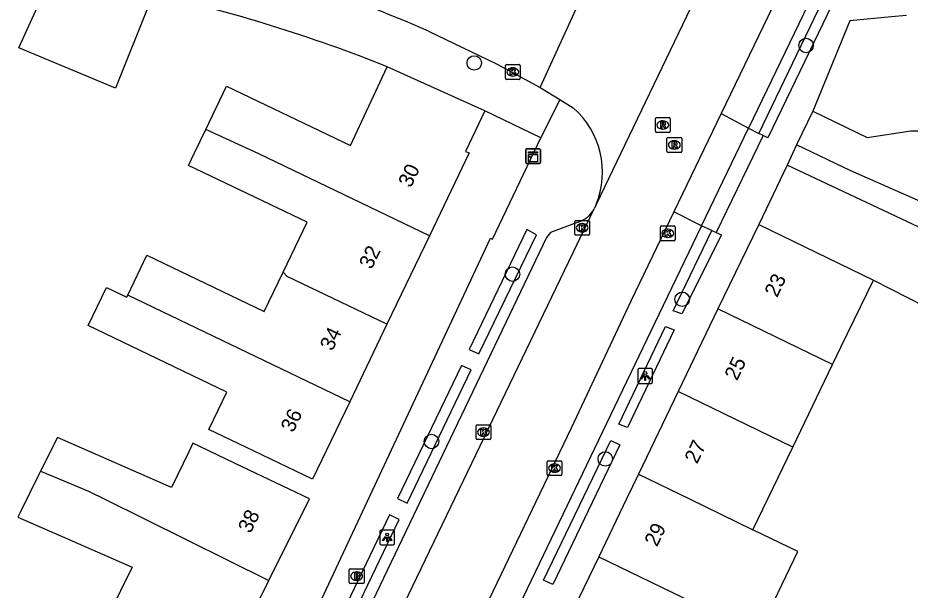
# Model space of a CAD drawing. Extents: x 163010 to 163853, y 382793 to 383982.
# Drawn here: x 163375.8 to 163436.2, y 383493.8 to 383532.5 of the extents above; entities that cross this region are included whole.
import ezdxf

# ---------------------------------------------------------------- set-up
doc = ezdxf.new("R2010")
doc.units = 0
for name, color, linetype in [('IMGEO_Boom', 7, 'Continuous'), ('IMGEO_Brandkraan', 7, 'Continuous'), ('IMGEO_Kast', 7, 'Continuous'), ('IMGEO_Kolk', 7, 'Continuous'), ('IMGEO_Lichtpunt', 7, 'Continuous'), ('IMGEO_Muur', 7, 'Continuous'), ('IMGEO_Pand', 7, 'Continuous'), ('IMGEO_Pand_nummerreeks', 7, 'Continuous'), ('IMGEO_Rijbaan_lokaal_gesloten', 7, 'Continuous'), ('IMGEO_Rijbaan_lokaal_onverhard', 7, 'Continuous'), ('IMGEO_Rijbaan_lokaal_open', 7, 'Continuous'), ('IMGEO_Rioolput', 7, 'Continuous'), ('IMGEO_Voetpad_open', 7, 'Continuous')]:
    doc.layers.add(name, color=color, linetype=linetype)

msp = doc.modelspace()

# ---------------------------------------------------------------- linework, layer by layer
at = {"layer": 'IMGEO_Boom'}
for centre in [(163429.168, 383530.666), (163406.72, 383529.486), (163409.304, 383515.2), (163420.79, 383513.503), (163403.821, 383503.888), (163415.582, 383502.708)]:
    msp.add_circle(centre, 0.489, dxfattribs=at)
at = {"layer": 'IMGEO_Brandkraan'}
for p, q in [((163398.259, 383494.356), (163398.259, 383495.208)), ((163398.334, 383495.282), (163399.186, 383495.282)), ((163398.747, 383495.062), (163398.772, 383495.062)), ((163399.26, 383495.208), (163399.26, 383494.356)), ((163398.77, 383494.502), (163398.745, 383494.502)), ((163399.186, 383494.282), (163398.334, 383494.282))]:
    msp.add_line(p, q, dxfattribs=at)
for points in [[(163398.259, 383494.356), (163398.259, 383495.208)], [(163398.334, 383495.282), (163399.186, 383495.282)], [(163398.607, 383494.982), (163398.607, 383494.582), (163398.82, 383494.582)], [(163398.838, 383494.982), (163398.607, 383494.982)], [(163399.26, 383495.208), (163399.26, 383494.356)], [(163398.786, 383494.901), (163398.732, 383494.901), (163398.732, 383494.825)], [(163398.732, 383494.825), (163398.785, 383494.825)], [(163398.794, 383494.749), (163398.732, 383494.749), (163398.732, 383494.668)], [(163398.732, 383494.668), (163398.794, 383494.668)], [(163399.186, 383494.282), (163398.334, 383494.282)]]:
    msp.add_lwpolyline(points, dxfattribs=at)
for centre, radius, start, end in [((163398.336, 383495.206), 0.0765, 91.55205, 178.44795), ((163398.336, 383495.206), 0.0765, 91.55205, 178.44795), ((163398.842, 383494.837), 0.145, 59.4692, 91.53667), ((163398.867, 383494.884), 0.0922, 285.51372, 58.15012), ((163399.184, 383495.206), 0.0765, 1.55205, 88.44795), ((163399.184, 383495.206), 0.0765, 1.55205, 88.44795), ((163398.336, 383494.358), 0.0765, 181.55205, 268.44795), ((163398.336, 383494.358), 0.0765, 181.55205, 268.44795), ((163398.787, 383494.863), 0.0379, 267.82845, 90.93552), ((163398.795, 383494.708), 0.0404, 269.87594, 90.50774), ((163398.826, 383494.833), 0.251, 268.66757, 293.53466), ((163398.872, 383494.692), 0.105, 301.31148, 78.98903), ((163399.184, 383494.358), 0.0765, 271.55205, 358.44795), ((163399.184, 383494.358), 0.0765, 271.55205, 358.44795)]:
    msp.add_arc(centre, radius, start, end, dxfattribs=at)
for centre, major_axis, ratio, start_param, end_param in [((163398.746, 383494.782), (-0.387, 0.002), 0.722429, 4.712389, 7.853982), ((163398.771, 383494.782), (-0.39, 0.002), 0.717154, 1.570796, 4.712389)]:
    msp.add_ellipse(centre, major_axis=major_axis, ratio=ratio, start_param=start_param, end_param=end_param, dxfattribs=at)
at = {"layer": 'IMGEO_Kast'}
for p, q in [((163410.195, 383522.751), (163410.195, 383523.592)), ((163410.195, 383523.592), (163410.195, 383522.751)), ((163410.27, 383523.676), (163411.111, 383523.676)), ((163411.111, 383523.676), (163410.27, 383523.676)), ((163411.195, 383523.601), (163411.195, 383522.76)), ((163411.195, 383522.76), (163411.195, 383523.601)), ((163411.12, 383522.676), (163410.279, 383522.676)), ((163410.279, 383522.676), (163411.12, 383522.676))]:
    msp.add_line(p, q, dxfattribs=at)
for points in [[(163410.39, 383523.466), (163410.99, 383523.466), (163410.99, 383523.381), (163410.39, 383523.381), (163410.39, 383523.466)], [(163410.39, 383523.291), (163410.99, 383523.291), (163410.99, 383522.802), (163410.39, 383522.802), (163410.39, 383523.291)]]:
    msp.add_lwpolyline(points, dxfattribs=at)
msp.add_circle((163410.474, 383523.14), 0.0377, dxfattribs=at)
for centre, start, end in [((163410.273, 383523.598), 92.4484, 184.28452), ((163410.273, 383523.598), 92.4484, 184.28452), ((163411.117, 383523.598), 2.4484, 94.28452), ((163411.117, 383523.598), 2.4484, 94.28452), ((163410.273, 383522.754), 182.4484, 274.28452), ((163410.273, 383522.754), 182.4484, 274.28452), ((163411.117, 383522.754), 272.4484, 4.28452), ((163411.117, 383522.754), 272.4484, 4.28452)]:
    msp.add_arc(centre, 0.0779, start, end, dxfattribs=at)
at = {"layer": 'IMGEO_Kolk'}
for p, q in [((163408.9, 383529.375), (163409.752, 383529.375)), ((163408.825, 383528.449), (163408.825, 383529.301)), ((163409.313, 383529.155), (163409.338, 383529.155)), ((163409.826, 383529.301), (163409.826, 383528.449)), ((163409.752, 383528.375), (163408.9, 383528.375)), ((163409.336, 383528.595), (163409.311, 383528.595)), ((163413.519, 383517.912), (163413.519, 383518.764)), ((163413.594, 383518.838), (163414.446, 383518.838)), ((163414.007, 383518.618), (163414.032, 383518.618)), ((163414.52, 383518.764), (163414.52, 383517.912)), ((163419.386, 383518.462), (163420.238, 383518.462)), ((163414.03, 383518.058), (163414.005, 383518.058)), ((163419.311, 383517.536), (163419.311, 383518.388)), ((163419.799, 383518.242), (163419.824, 383518.242)), ((163420.312, 383518.388), (163420.312, 383517.536)), ((163414.446, 383517.838), (163413.594, 383517.838)), ((163420.238, 383517.462), (163419.386, 383517.462)), ((163419.822, 383517.682), (163419.797, 383517.682)), ((163406.839, 383504.094), (163406.839, 383504.946)), ((163406.914, 383505.02), (163407.766, 383505.02)), ((163407.327, 383504.8), (163407.352, 383504.8)), ((163407.84, 383504.946), (163407.84, 383504.094)), ((163407.766, 383504.02), (163406.914, 383504.02)), ((163407.35, 383504.24), (163407.325, 383504.24)), ((163411.649, 383501.66), (163411.649, 383502.512)), ((163411.724, 383502.586), (163412.576, 383502.586)), ((163412.137, 383502.366), (163412.162, 383502.366)), ((163412.65, 383502.512), (163412.65, 383501.66)), ((163412.576, 383501.586), (163411.724, 383501.586)), ((163412.16, 383501.806), (163412.135, 383501.806))]:
    msp.add_line(p, q, dxfattribs=at)
for points in [[(163408.9, 383529.375), (163409.752, 383529.375)], [(163408.825, 383528.449), (163408.825, 383529.301)], [(163409.146, 383529.075), (163409.269, 383529.075), (163409.269, 383528.924), (163409.399, 383529.075), (163409.563, 383529.075), (163409.417, 383528.924), (163409.57, 383528.675), (163409.418, 383528.675), (163409.333, 383528.839), (163409.269, 383528.772), (163409.269, 383528.675), (163409.146, 383528.675), (163409.146, 383529.075)], [(163409.826, 383529.301), (163409.826, 383528.449)], [(163409.752, 383528.375), (163408.9, 383528.375)], [(163413.519, 383517.912), (163413.519, 383518.764)], [(163413.594, 383518.838), (163414.446, 383518.838)], [(163413.84, 383518.538), (163413.963, 383518.538), (163413.963, 383518.387), (163414.093, 383518.538), (163414.257, 383518.538), (163414.111, 383518.387), (163414.264, 383518.138), (163414.112, 383518.138), (163414.027, 383518.302), (163413.963, 383518.235), (163413.963, 383518.138), (163413.84, 383518.138), (163413.84, 383518.538)], [(163414.52, 383518.764), (163414.52, 383517.912)], [(163419.386, 383518.462), (163420.238, 383518.462)], [(163419.311, 383517.536), (163419.311, 383518.388)], [(163419.632, 383518.162), (163419.755, 383518.162), (163419.755, 383518.011), (163419.885, 383518.162), (163420.049, 383518.162), (163419.903, 383518.011), (163420.056, 383517.762), (163419.904, 383517.762), (163419.819, 383517.926), (163419.755, 383517.859), (163419.755, 383517.762), (163419.632, 383517.762), (163419.632, 383518.162)], [(163420.312, 383518.388), (163420.312, 383517.536)], [(163414.446, 383517.838), (163413.594, 383517.838)], [(163420.238, 383517.462), (163419.386, 383517.462)], [(163406.839, 383504.094), (163406.839, 383504.946)], [(163406.914, 383505.02), (163407.766, 383505.02)], [(163407.16, 383504.72), (163407.283, 383504.72), (163407.283, 383504.569), (163407.413, 383504.72), (163407.577, 383504.72), (163407.431, 383504.569), (163407.584, 383504.32), (163407.432, 383504.32), (163407.347, 383504.484), (163407.283, 383504.417), (163407.283, 383504.32), (163407.16, 383504.32), (163407.16, 383504.72)], [(163407.84, 383504.946), (163407.84, 383504.094)], [(163407.766, 383504.02), (163406.914, 383504.02)], [(163411.649, 383501.66), (163411.649, 383502.512)], [(163411.724, 383502.586), (163412.576, 383502.586)], [(163411.97, 383502.286), (163412.093, 383502.286), (163412.093, 383502.135), (163412.223, 383502.286), (163412.387, 383502.286), (163412.241, 383502.135), (163412.394, 383501.886), (163412.242, 383501.886), (163412.157, 383502.05), (163412.093, 383501.983), (163412.093, 383501.886), (163411.97, 383501.886), (163411.97, 383502.286)], [(163412.65, 383502.512), (163412.65, 383501.66)], [(163412.576, 383501.586), (163411.724, 383501.586)]]:
    msp.add_lwpolyline(points, dxfattribs=at)
for centre, start, end in [((163408.902, 383529.299), 91.55205, 178.44795), ((163408.902, 383529.299), 91.55205, 178.44795), ((163409.75, 383529.299), 1.55205, 88.44795), ((163409.75, 383529.299), 1.55205, 88.44795), ((163408.902, 383528.451), 181.55205, 268.44795), ((163408.902, 383528.451), 181.55205, 268.44795), ((163409.75, 383528.451), 271.55205, 358.44795), ((163409.75, 383528.451), 271.55205, 358.44795), ((163413.596, 383518.762), 91.55205, 178.44795), ((163413.596, 383518.762), 91.55205, 178.44795), ((163414.444, 383518.762), 1.55205, 88.44795), ((163414.444, 383518.762), 1.55205, 88.44795), ((163419.388, 383518.386), 91.55205, 178.44795), ((163419.388, 383518.386), 91.55205, 178.44795), ((163420.236, 383518.386), 1.55205, 88.44795), ((163420.236, 383518.386), 1.55205, 88.44795), ((163413.596, 383517.914), 181.55205, 268.44795), ((163413.596, 383517.914), 181.55205, 268.44795), ((163414.444, 383517.914), 271.55205, 358.44795), ((163414.444, 383517.914), 271.55205, 358.44795), ((163419.388, 383517.538), 181.55205, 268.44795), ((163419.388, 383517.538), 181.55205, 268.44795), ((163420.236, 383517.538), 271.55205, 358.44795), ((163420.236, 383517.538), 271.55205, 358.44795), ((163406.916, 383504.944), 91.55205, 178.44795), ((163406.916, 383504.944), 91.55205, 178.44795), ((163407.764, 383504.944), 1.55205, 88.44795), ((163407.764, 383504.944), 1.55205, 88.44795), ((163406.916, 383504.096), 181.55205, 268.44795), ((163406.916, 383504.096), 181.55205, 268.44795), ((163407.764, 383504.096), 271.55205, 358.44795), ((163407.764, 383504.096), 271.55205, 358.44795), ((163411.726, 383502.51), 91.55205, 178.44795), ((163411.726, 383502.51), 91.55205, 178.44795), ((163412.574, 383502.51), 1.55205, 88.44795), ((163412.574, 383502.51), 1.55205, 88.44795), ((163411.726, 383501.662), 181.55205, 268.44795), ((163411.726, 383501.662), 181.55205, 268.44795), ((163412.574, 383501.662), 271.55205, 358.44795), ((163412.574, 383501.662), 271.55205, 358.44795)]:
    msp.add_arc(centre, 0.0765, start, end, dxfattribs=at)
for centre, major_axis, ratio, start_param, end_param in [((163409.312, 383528.875), (-0.387, 0.002), 0.722429, 4.712389, 7.853982), ((163409.337, 383528.875), (-0.39, 0.002), 0.717154, 1.570796, 4.712389), ((163414.006, 383518.338), (-0.387, 0.002), 0.722429, 4.712389, 7.853982), ((163414.031, 383518.338), (-0.39, 0.002), 0.717154, 1.570796, 4.712389), ((163419.798, 383517.962), (-0.387, 0.002), 0.722429, 4.712389, 7.853982), ((163419.823, 383517.962), (-0.39, 0.002), 0.717154, 1.570796, 4.712389), ((163407.326, 383504.52), (-0.387, 0.002), 0.722429, 4.712389, 7.853982), ((163407.351, 383504.52), (-0.39, 0.002), 0.717154, 1.570796, 4.712389), ((163412.136, 383502.086), (-0.387, 0.002), 0.722429, 4.712389, 7.853982), ((163412.161, 383502.086), (-0.39, 0.002), 0.717154, 1.570796, 4.712389)]:
    msp.add_ellipse(centre, major_axis=major_axis, ratio=ratio, start_param=start_param, end_param=end_param, dxfattribs=at)
at = {"layer": 'IMGEO_Lichtpunt'}
for p, q in [((163418.694, 383508.813), (163417.886, 383508.813)), ((163418.694, 383508.813), (163417.886, 383508.813)), ((163417.792, 383508.718), (163417.792, 383507.911)), ((163417.792, 383508.718), (163417.792, 383507.911)), ((163418.788, 383507.911), (163418.788, 383508.718)), ((163418.788, 383507.911), (163418.788, 383508.718)), ((163417.886, 383507.817), (163418.694, 383507.817)), ((163417.886, 383507.817), (163418.694, 383507.817)), ((163400.324, 383497.799), (163400.324, 383496.992)), ((163400.324, 383497.799), (163400.324, 383496.992)), ((163401.226, 383497.894), (163400.418, 383497.894)), ((163401.226, 383497.894), (163400.418, 383497.894)), ((163401.32, 383496.992), (163401.32, 383497.799)), ((163401.32, 383496.992), (163401.32, 383497.799)), ((163400.418, 383496.898), (163401.226, 383496.898)), ((163400.418, 383496.898), (163401.226, 383496.898))]:
    msp.add_line(p, q, dxfattribs=at)
for points in [[(163418.166, 383508.382), (163418.205, 383508.354), (163418.017, 383508.092), (163417.979, 383508.119), (163418.166, 383508.382)], [(163418.268, 383508.334), (163418.315, 383508.334), (163418.315, 383508.012), (163418.268, 383508.012), (163418.268, 383508.334)], [(163418.378, 383508.354), (163418.416, 383508.381), (163418.603, 383508.119), (163418.564, 383508.091), (163418.378, 383508.354)], [(163400.698, 383497.463), (163400.737, 383497.435), (163400.549, 383497.173), (163400.511, 383497.2), (163400.698, 383497.463)], [(163400.8, 383497.415), (163400.847, 383497.415), (163400.847, 383497.093), (163400.8, 383497.093), (163400.8, 383497.415)], [(163400.91, 383497.435), (163400.948, 383497.462), (163401.135, 383497.2), (163401.096, 383497.172), (163400.91, 383497.435)]]:
    msp.add_lwpolyline(points, dxfattribs=at)
for centre in [(163418.291, 383508.516), (163400.823, 383497.597)]:
    msp.add_circle(centre, 0.0994, dxfattribs=at)
for centre, start, end in [((163417.886, 383508.718), 90, 180), ((163417.886, 383508.718), 90, 180), ((163418.694, 383508.718), 0, 90), ((163418.694, 383508.718), 0, 90), ((163417.886, 383507.911), 180, 270), ((163417.886, 383507.911), 180, 270), ((163418.694, 383507.911), 270, 0), ((163418.694, 383507.911), 270, 360), ((163400.418, 383497.799), 90, 180), ((163400.418, 383497.799), 90, 180), ((163401.226, 383497.799), 0, 90), ((163401.226, 383497.799), 0, 90), ((163400.418, 383496.992), 180, 270), ((163400.418, 383496.992), 180, 270), ((163401.226, 383496.992), 270, 0), ((163401.226, 383496.992), 270, 360)]:
    msp.add_arc(centre, 0.0946, start, end, dxfattribs=at)
at = {"layer": 'IMGEO_Muur'}
for points in [[(163432.139, 383532.338), (163429.633, 383526.219)], [(163433.726, 383514.797), (163441.793, 383510.691)]]:
    msp.add_lwpolyline(points, dxfattribs=at)
msp.add_arc((163361.756, 383431.525), 105.221, 68.21207, 77.24489, dxfattribs=at)
at = {"layer": 'IMGEO_Pand'}
for points in [[(163375.895, 383530.496), (163377.833, 383534.788), (163384.752, 383533.563), (163382.435, 383527.774), (163375.895, 383530.496)], [(163388.544, 383524.982), (163389.954, 383527.92), (163398.34, 383523.895), (163400.811, 383529.23)], [(163407.421, 383526.246), (163400.811, 383529.23)], [(163407.421, 383526.246), (163406.122, 383523.495), (163406.375, 383523.406), (163403.679, 383517.795)], [(163429.633, 383526.219), (163428.534, 383523.951)], [(163429.633, 383526.219), (163433.296, 383524.445), (163436.265, 383524.895), (163442.07, 383524.895), (163442.446, 383519.77), (163442.604, 383517.614)], [(163393.775, 383515.325), (163395.399, 383518.71), (163387.381, 383522.557), (163387.791, 383523.412), (163388.544, 383524.982)], [(163403.679, 383517.795), (163392.146, 383523.335), (163388.544, 383524.982)], [(163442.604, 383517.614), (163432.199, 383522.177), (163428.534, 383523.951)], [(163425.964, 383518.558), (163423.211, 383512.846)], [(163425.964, 383518.558), (163433.726, 383514.797)], [(163403.679, 383517.795), (163400.802, 383511.808)], [(163383.263, 383513.788), (163384.561, 383516.493), (163392.507, 383512.681), (163393.775, 383515.325)], [(163400.802, 383511.808), (163394.05, 383515.051), (163393.775, 383515.325)], [(163398.285, 383506.571), (163395.768, 383501.333), (163391.26, 383503.496), (163388.755, 383504.698), (163389.966, 383507.22), (163380.591, 383511.718), (163381.831, 383514.302), (163383.195, 383513.647), (163383.263, 383513.788)], [(163430.96, 383509.085), (163431.546, 383510.298), (163433.726, 383514.797)], [(163398.285, 383506.571), (163383.263, 383513.788)], [(163423.211, 383512.846), (163420.52, 383507.261)], [(163430.96, 383509.085), (163423.211, 383512.846)], [(163400.802, 383511.808), (163398.285, 383506.571)], [(163428.266, 383503.5), (163430.96, 383509.085)], [(163420.52, 383507.261), (163417.828, 383501.675)], [(163428.266, 383503.5), (163420.52, 383507.261)], [(163392.824, 383494.479), (163395.558, 383500), (163391.009, 383502.182), (163387.675, 383503.781), (163387.388, 383503.183), (163386.235, 383500.78), (163378.51, 383504.166), (163377.371, 383501.873)], [(163425.572, 383497.917), (163426.577, 383500), (163428.266, 383503.5)], [(163377.371, 383501.873), (163377.257, 383501.643), (163376.01, 383499.133), (163375.827, 383498.764), (163379.178, 383497.298), (163383.561, 383495.38), (163381.957, 383492.15)], [(163377.371, 383501.873), (163378.231, 383501.513), (163380.613, 383500.517), (163380.701, 383500.474), (163381.659, 383500), (163392.824, 383494.479)], [(163417.828, 383501.675), (163417.021, 383500), (163415.137, 383496.091)], [(163417.828, 383501.675), (163421.279, 383500), (163425.572, 383497.917)], [(163422.877, 383492.334), (163425.927, 383490.854), (163428.622, 383496.437), (163425.572, 383497.917)], [(163415.137, 383496.091), (163412.445, 383490.505)], [(163415.137, 383496.091), (163422.877, 383492.334)], [(163389.832, 383488.435), (163392.824, 383494.479)]]:
    msp.add_lwpolyline(points, dxfattribs=at)
at = {"layer": 'IMGEO_Rijbaan_lokaal_gesloten'}
for points in [[(163429.106, 383537.857), (163423.429, 383526.069)], [(163422.471, 383535.55), (163414.963, 383519.907)], [(163411.172, 383527.832), (163414.086, 383534.211)], [(163411.172, 383527.832), (163412.503, 383527.01)], [(163412.503, 383527.01), (163413.416, 383526.445)], [(163423.429, 383526.069), (163420.226, 383519.418)], [(163414.963, 383519.907), (163414.821, 383519.619)], [(163387.99, 383463.854), (163414.821, 383519.619)], [(163420.226, 383519.418), (163417.318, 383513.38), (163413.28, 383504.776), (163392.631, 383461.788)]]:
    msp.add_lwpolyline(points, dxfattribs=at)
msp.add_arc((163409.628, 383522.097), 5.767, 337.68649, 48.93811, dxfattribs=at)
at = {"layer": 'IMGEO_Rijbaan_lokaal_onverhard'}
for points in [[(163427.893, 383522.56), (163425.964, 383518.558)], [(163449.585, 383515.939), (163442.932, 383515.502), (163427.893, 383522.56)], [(163433.726, 383514.797), (163441.793, 383510.691)]]:
    msp.add_lwpolyline(points, dxfattribs=at)
at = {"layer": 'IMGEO_Rijbaan_lokaal_open'}
msp.add_lwpolyline([(163403.621, 383531.641), (163408.214, 383529.426), (163411.172, 383527.832)], dxfattribs=at)
msp.add_arc((163364.957, 383442.706), 96.976, 66.50318, 71.81796, dxfattribs=at)
at = {"layer": 'IMGEO_Rioolput'}
for p, q in [((163418.976, 383524.862), (163418.976, 383525.714)), ((163419.051, 383525.788), (163419.903, 383525.788)), ((163419.977, 383525.714), (163419.977, 383524.862)), ((163419.464, 383525.568), (163419.489, 383525.568)), ((163419.903, 383524.788), (163419.051, 383524.788)), ((163419.487, 383525.008), (163419.462, 383525.008)), ((163419.754, 383523.512), (163419.754, 383524.364)), ((163419.829, 383524.438), (163420.681, 383524.438)), ((163420.242, 383524.218), (163420.267, 383524.218)), ((163420.755, 383524.364), (163420.755, 383523.512)), ((163420.681, 383523.438), (163419.829, 383523.438)), ((163420.265, 383523.658), (163420.24, 383523.658))]:
    msp.add_line(p, q, dxfattribs=at)
for points in [[(163418.976, 383524.862), (163418.976, 383525.714)], [(163419.051, 383525.788), (163419.903, 383525.788)], [(163419.977, 383525.714), (163419.977, 383524.862)], [(163419.565, 383525.486), (163419.313, 383525.488), (163419.313, 383525.088)], [(163419.313, 383525.088), (163419.437, 383525.088), (163419.437, 383525.25), (163419.448, 383525.25)], [(163419.491, 383525.407), (163419.437, 383525.407), (163419.437, 383525.326)], [(163419.437, 383525.326), (163419.489, 383525.326)], [(163419.495, 383525.221), (163419.566, 383525.088), (163419.706, 383525.088), (163419.641, 383525.214)], [(163419.903, 383524.788), (163419.051, 383524.788)], [(163419.754, 383523.512), (163419.754, 383524.364)], [(163419.829, 383524.438), (163420.681, 383524.438)], [(163420.343, 383524.136), (163420.091, 383524.138), (163420.091, 383523.738)], [(163420.091, 383523.738), (163420.215, 383523.738), (163420.215, 383523.9), (163420.226, 383523.9)], [(163420.269, 383524.057), (163420.215, 383524.057), (163420.215, 383523.976)], [(163420.215, 383523.976), (163420.267, 383523.976)], [(163420.755, 383524.364), (163420.755, 383523.512)], [(163420.681, 383523.438), (163419.829, 383523.438)], [(163420.273, 383523.871), (163420.344, 383523.738), (163420.484, 383523.738), (163420.419, 383523.864)]]:
    msp.add_lwpolyline(points, dxfattribs=at)
for centre, radius, start, end in [((163419.053, 383525.712), 0.0765, 91.55205, 178.44795), ((163419.053, 383525.712), 0.0765, 91.55205, 178.44795), ((163419.901, 383525.712), 0.0765, 1.55205, 88.44795), ((163419.901, 383525.712), 0.0765, 1.55205, 88.44795), ((163419.447, 383525.197), 0.0533, 26.02933, 88.69889), ((163419.473, 383525.515), 0.19, 274.7715, 282.96867), ((163419.497, 383525.311), 0.0964, 77.00612, 93.18647), ((163419.511, 383525.368), 0.0378, 276.66336, 79.67722), ((163419.564, 383525.376), 0.109, 350.36119, 89.41601), ((163419.562, 383525.376), 0.112, 277.58423, 350.98172), ((163419.546, 383525.161), 0.108, 29.51342, 73.79051), ((163419.053, 383524.864), 0.0765, 181.55205, 268.44795), ((163419.053, 383524.864), 0.0765, 181.55205, 268.44795), ((163419.901, 383524.864), 0.0765, 271.55205, 358.44795), ((163419.901, 383524.864), 0.0765, 271.55205, 358.44795), ((163419.831, 383524.362), 0.0765, 91.55205, 178.44795), ((163419.831, 383524.362), 0.0765, 91.55205, 178.44795), ((163420.225, 383523.847), 0.0533, 26.02933, 88.69889), ((163420.251, 383524.165), 0.19, 274.7715, 282.96867), ((163420.275, 383523.961), 0.0964, 77.00612, 93.18647), ((163420.289, 383524.018), 0.0378, 276.66336, 79.67722), ((163420.342, 383524.026), 0.109, 350.36119, 89.41601), ((163420.34, 383524.026), 0.112, 277.58423, 350.98172), ((163420.324, 383523.811), 0.108, 29.51342, 73.79051), ((163420.679, 383524.362), 0.0765, 1.55205, 88.44795), ((163420.679, 383524.362), 0.0765, 1.55205, 88.44795), ((163419.831, 383523.514), 0.0765, 181.55205, 268.44795), ((163419.831, 383523.514), 0.0765, 181.55205, 268.44795), ((163420.679, 383523.514), 0.0765, 271.55205, 358.44795), ((163420.679, 383523.514), 0.0765, 271.55205, 358.44795)]:
    msp.add_arc(centre, radius, start, end, dxfattribs=at)
for centre, major_axis, ratio, start_param, end_param in [((163419.463, 383525.288), (-0.387, 0.002), 0.722429, 4.712389, 7.853982), ((163419.488, 383525.288), (-0.39, 0.002), 0.717154, 1.570796, 4.712389), ((163420.241, 383523.938), (-0.387, 0.002), 0.722429, 4.712389, 7.853982), ((163420.266, 383523.938), (-0.39, 0.002), 0.717154, 1.570796, 4.712389)]:
    msp.add_ellipse(centre, major_axis=major_axis, ratio=ratio, start_param=start_param, end_param=end_param, dxfattribs=at)
at = {"layer": 'IMGEO_Voetpad_open'}
for points in [[(163429.613, 383534.075), (163425.279, 383525.075)], [(163425.981, 383524.719), (163430.296, 383533.716), (163430.908, 383533.399), (163426.593, 383524.409), (163426.273, 383524.571)], [(163435.97, 383532.7), (163434.943, 383532.603), (163432.139, 383532.338), (163429.633, 383526.219)], [(163412.503, 383527.01), (163411.222, 383524.423)], [(163411.222, 383524.423), (163407.421, 383526.246)], [(163423.429, 383526.069), (163425.279, 383525.075)], [(163422.1, 383518.475), (163425.279, 383525.075)], [(163426.273, 383524.571), (163423.082, 383518.015)], [(163425.279, 383525.075), (163425.981, 383524.719)], [(163426.273, 383524.571), (163425.981, 383524.719)], [(163380.048, 383459.98), (163393.082, 383486.146), (163394.744, 383489.722), (163407.819, 383517.643), (163407.958, 383517.577), (163411.222, 383524.423)], [(163428.534, 383523.951), (163427.893, 383522.56)], [(163422.1, 383518.475), (163420.226, 383519.418)], [(163413.75, 383518.724), (163411.879, 383518.024), (163411.615, 383517.682), (163397.565, 383488.367), (163387.651, 383467.78)], [(163422.1, 383518.475), (163419.208, 383512.47), (163415.113, 383503.981), (163395.804, 383463.766)], [(163422.791, 383518.147), (163422.1, 383518.475)], [(163407.03, 383509.805), (163410.929, 383517.868), (163410.284, 383518.213), (163406.37, 383510.111), (163407.03, 383509.805)], [(163423.082, 383518.015), (163423.444, 383517.851), (163420.76, 383512.525), (163420.18, 383512.732), (163422.791, 383518.147)], [(163422.791, 383518.147), (163423.082, 383518.015)], [(163420.239, 383511.443), (163417.08, 383504.831), (163416.49, 383505.055), (163419.666, 383511.661), (163420.239, 383511.443)], [(163405.85, 383509.032), (163401.514, 383500.027), (163402.172, 383499.711), (163406.51, 383508.724), (163405.85, 383509.032)], [(163416.572, 383503.666), (163412.027, 383494.208), (163411.403, 383494.508), (163415.948, 383503.949), (163416.572, 383503.666)], [(163396.224, 383489.011), (163396.872, 383488.7), (163401.64, 383498.606), (163400.987, 383498.92), (163396.224, 383489.011)]]:
    msp.add_lwpolyline(points, dxfattribs=at)
for centre, radius, start, end in [((163361.756, 383431.525), 105.221, 68.21207, 77.24489), ((163413.214, 383520.454), 1.811, 287.21609, 332.55274)]:
    msp.add_arc(centre, radius, start, end, dxfattribs=at)

# ---------------------------------------------------------------- texts
at = {"layer": 'IMGEO_Pand_nummerreeks'}
for s, rotation, p in [('30', 64.33377, (163402.421, 383520.996)), ('32', 64.33377, (163399.767, 383515.473)), ('23', 64.32096, (163427.208, 383513.576)), ('34', 64.33377, (163397.116, 383509.956)), ('25', 64.32096, (163424.501, 383507.946)), ('36', 64.33377, (163394.464, 383504.438)), ('27', 64.32096, (163421.794, 383502.316)), ('38', 63.66134, (163391.567, 383497.619)), ('29', 64.26895, (163419.079, 383496.714))]:
    msp.add_text(s, height=1, rotation=rotation, dxfattribs=at).set_placement(p)

doc.saveas('drawing.dxf')
